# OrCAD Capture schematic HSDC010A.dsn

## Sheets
1 DATA: size B; title: TFP401EVM HSDC010; rev: A
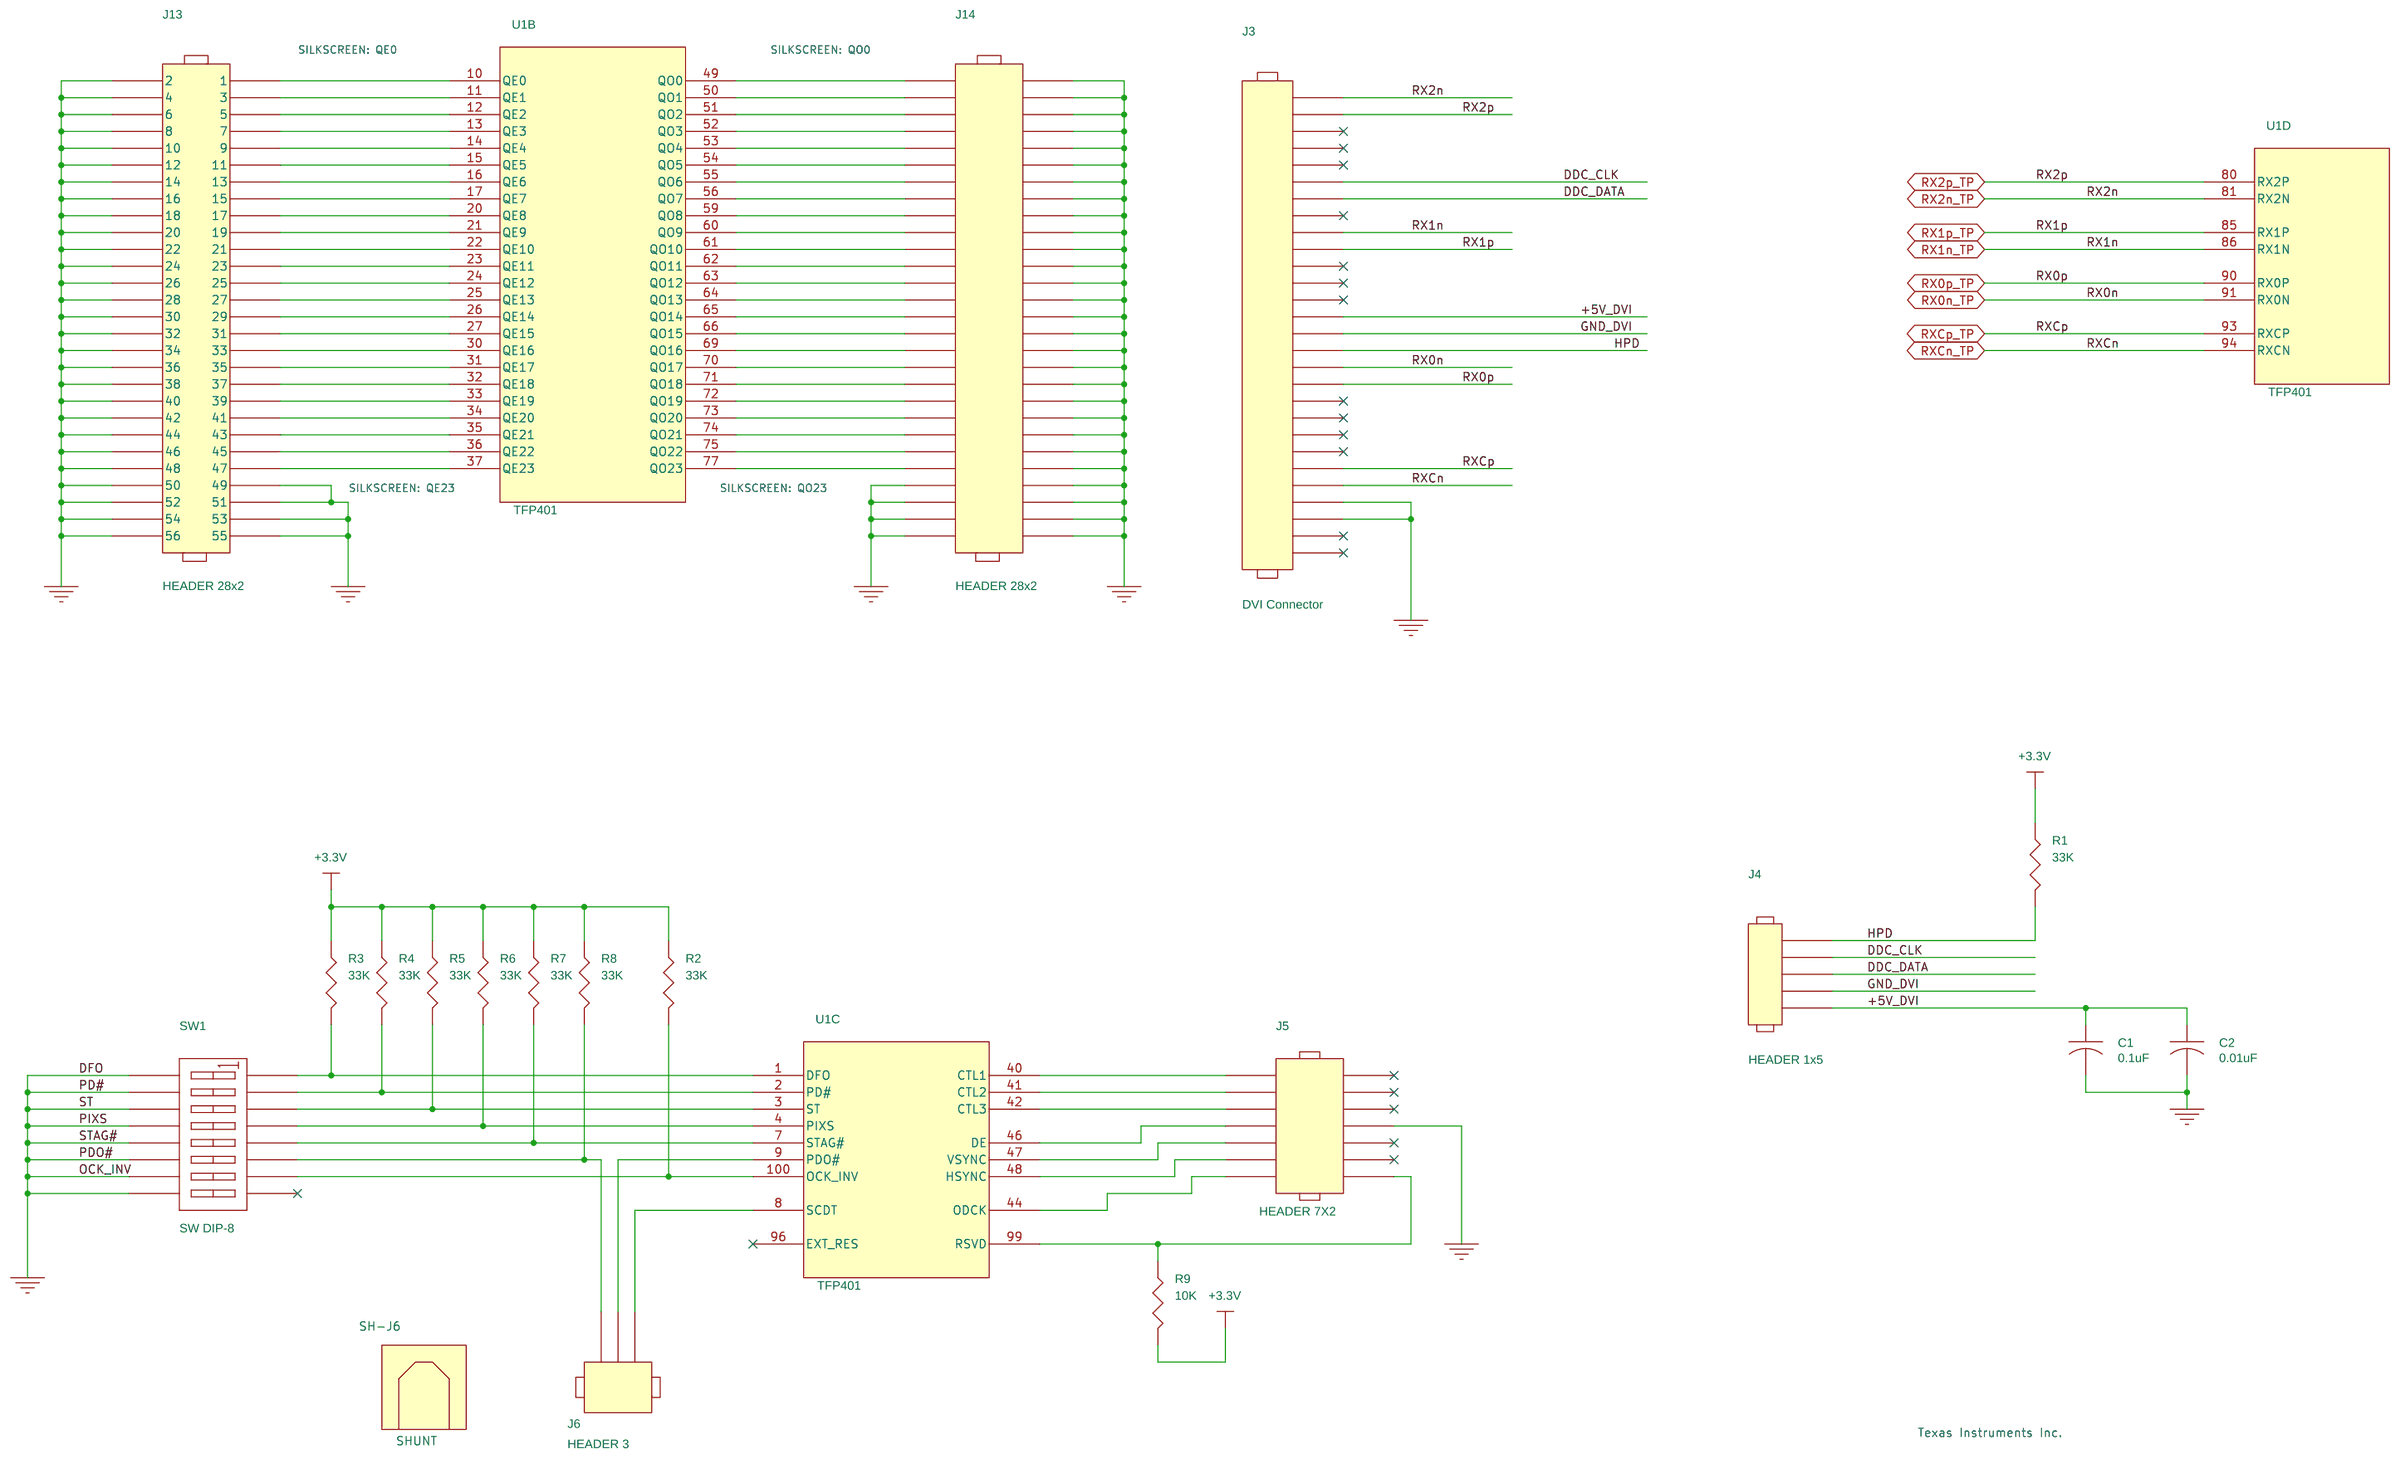
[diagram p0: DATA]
2 MISC: size B
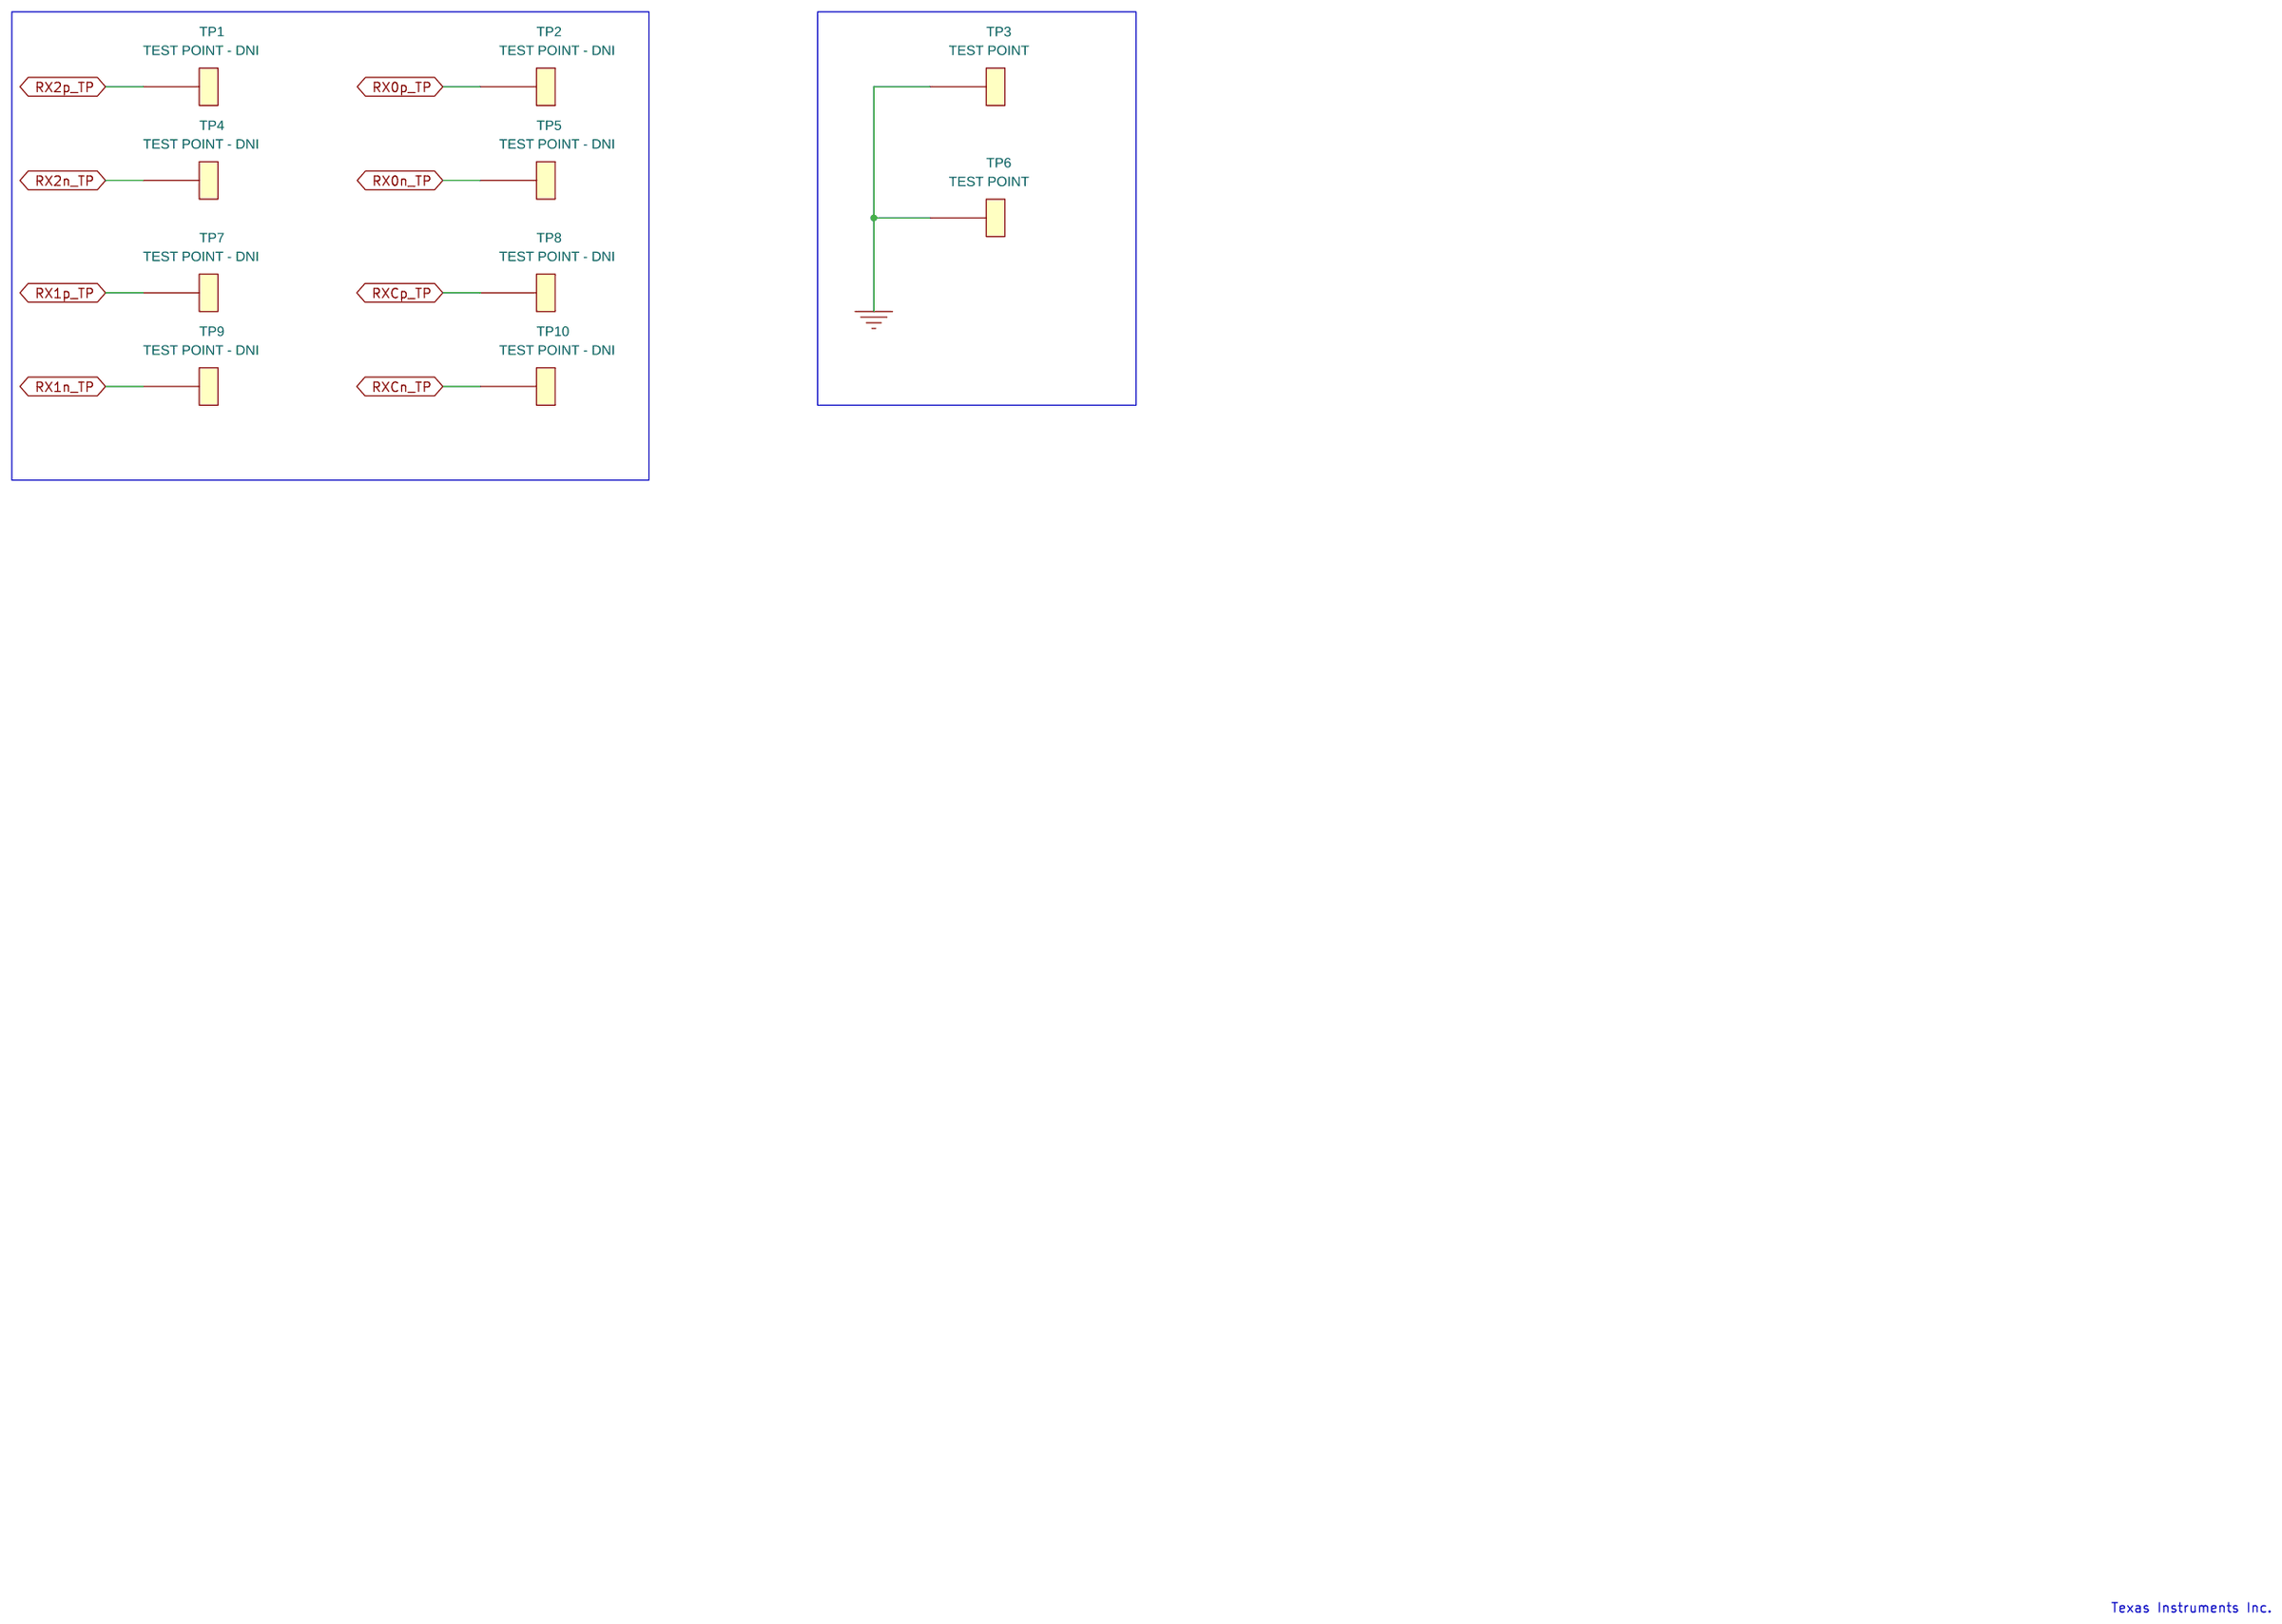
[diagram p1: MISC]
3 Power: size B
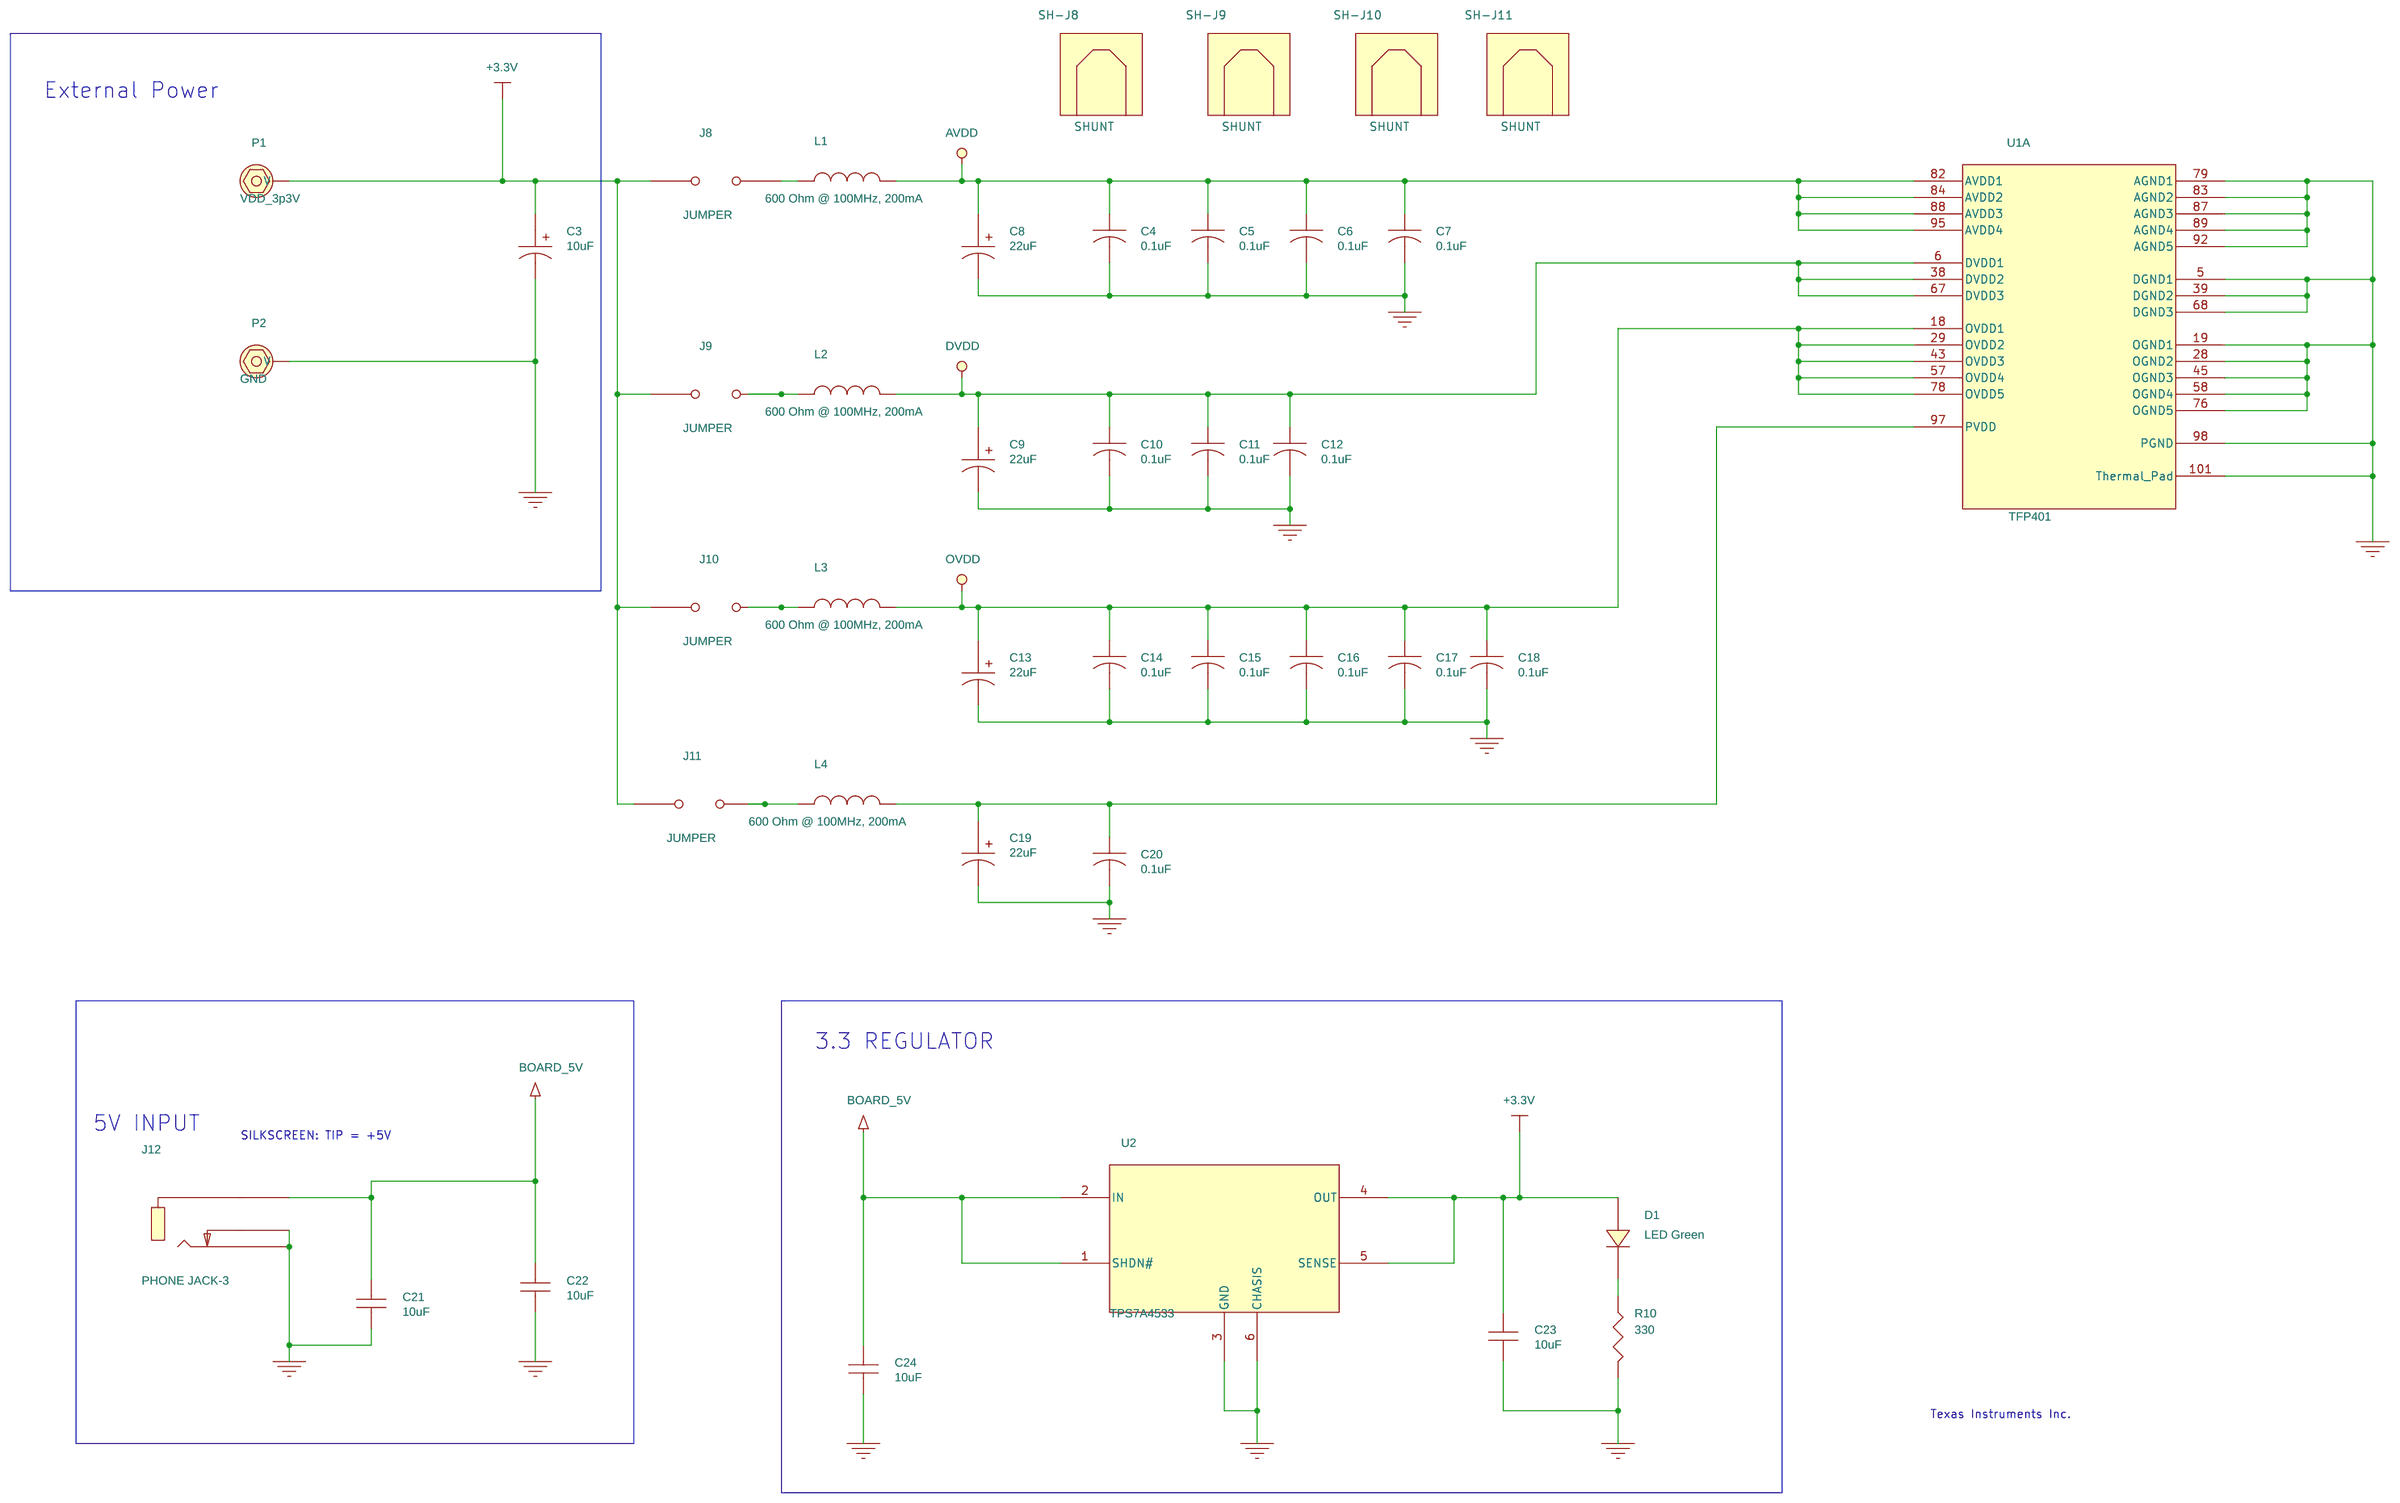
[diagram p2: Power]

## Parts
sheet DATA
C1  0.1uF  [cc0603]
C2  0.01uF  [cc0603]
J3  DVI Connector  [DVI_conn_01]
J4  HEADER 1x5  [berg1x5]
J5  HEADER 7X2  [berg2x7]
J6  HEADER 3  [hdr_thvt_1x3_100]
J13  HEADER 28x2  [header2x28]
J14  HEADER 28x2  [header2x28]
R1  33K  [r0402]
R2  33K  [r0402]
R3  33K  [r0402]
R4  33K  [r0402]
R5  33K  [r0402]
R6  33K  [r0402]
R7  33K  [r0402]
R8  33K  [r0402]
R9  10K  [r0402]
SH-J6  SHUNT
SW1  SW DIP-8  [TDA08H0SK1]
sheet MISC
TP1  TEST POINT - DNI  [TestPointSMT_1]
TP2  TEST POINT - DNI  [TestPointSMT_1]
TP3  TEST POINT  [berg1x1]
TP4  TEST POINT - DNI  [TestPointSMT_1]
TP5  TEST POINT - DNI  [TestPointSMT_1]
TP6  TEST POINT  [berg1x1]
TP7  TEST POINT - DNI  [TestPointSMT_1]
TP8  TEST POINT - DNI  [TestPointSMT_1]
TP9  TEST POINT - DNI  [TestPointSMT_1]
TP10  TEST POINT - DNI  [TestPointSMT_1]
sheet Power
C3  10uF  [cc0805]
C4  0.1uF  [cc0603]
C5  0.1uF  [cc0603]
C6  0.1uF  [cc0603]
C7  0.1uF  [cc0603]
C8  22uF  [cc0805]
C9  22uF  [cc0805]
C10  0.1uF  [cc0603]
C11  0.1uF  [cc0603]
C12  0.1uF  [cc0603]
C13  22uF  [cc0805]
C14  0.1uF  [cc0603]
C15  0.1uF  [cc0603]
C16  0.1uF  [cc0603]
C17  0.1uF  [cc0603]
C18  0.1uF  [cc0603]
C19  22uF  [cc0805]
C20  0.1uF  [cc0603]
C21  10uF  [cc0805]
C22  10uF  [cc0805]
C23  10uF  [cc0805]
C24  10uF  [cc0805]
D1  LED Green  [r0805]
J8  JUMPER  [berg1x2]
J9  JUMPER  [berg1x2]
J10  JUMPER  [berg1x2]
J11  JUMPER  [berg1x2]
J12  PHONE JACK-3  [PJ-202AH]
L1  600 Ohm @ 100MHz, 200mA  [CAP0603]
L2  600 Ohm @ 100MHz, 200mA  [CAP0603]
L3  600 Ohm @ 100MHz, 200mA  [CAP0603]
L4  600 Ohm @ 100MHz, 200mA  [CAP0603]
P1  Banana-Jack  [Banana_Jack_250mil]
P2  Banana-Jack  [Banana_Jack_250mil]
R10  330  [r0402]
SH-J8  SHUNT
SH-J9  SHUNT
SH-J10  SHUNT
SH-J11  SHUNT
U1  TFP401  [pzp-s-pqfp-g100]  (sections A,B,C,D)
U2  TPS7A4533  [dcq_r-pdso-g6]

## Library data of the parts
C1 C2 C4-C7 C10-C12 C14-C18 C20 = CAP
J3 = HEADER_28
J4 = HEADER_5
J5 = HEADER_7X2
J6 = HEADER_3
J13 = HEADER_28x2_0
J14 = HEADER_28x2
R1-R10 = R
SH-J6 SH-J8-SH-J11 = SHUNT
SW1 = SW_DIP-8
TP1 = TEST_POINT_0: Open pads
TP2 TP4 TP5 TP7-TP10 = TEST_POINT_0: OPEN PADS
TP3 TP6 = TEST_POINT_0: EST POINT PC MULTI PURPOSE BLK
C3 C8 C9 C13 C19 = CAP_POL
C21-C24 = CAP_NP
D1 = DIODE
J8-J11 = JUMPER
J12 = PHONE_JACK-3_0
L1-L4 = INDUCTOR
P1 = Banana-Jack: SILKTEXT1: VDD_3p3V; SILKTEXT2: VDD_3p3V
P2 = Banana-Jack: SILKTEXT1: GND; SILKTEXT2: GND
U1 = TFP401
U2 = TPS7A4533

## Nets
+3.3V: C3.1 C23.1 D1.2(A) J8.1 J9.1 J10.1 J11.1 P1.1(V) R1.1 R2.1 R3.1 R4.1 R5.1 R6.1 R7.1 R8.1 R9.2 U2.4(OUT) U2.5(SENSE)
+5V_DVI: C1.1 C2.1 J3.14 J4.5
AVDD: C4.1 C5.1 C6.1 C7.1 C8.1 L1.2 U1.82(AVDD1) U1.84(AVDD2) U1.88(AVDD3) U1.95(AVDD4)
DVDD: C9.1 C10.1 C11.1 C12.1 L2.2 U1.6(DVDD1) U1.38(DVDD2) U1.67(DVDD3)
GND_DVI: J3.15 J4.4
GND_POWER: C1.2 C2.2 C3.2 C4.2 C5.2 C6.2 C7.2 C8.2 C9.2 C10.2 C11.2 C12.2 C13.2 C14.2 C15.2 C16.2 C17.2 C18.2 C19.2 C20.2 C21.2 C22.2 C23.2 C24.2 J3.25 J3.26 J5.7 J12.2 J12.3 J13.1(55) J13.2(56) J13.3(53) J13.4(54) J13.5(51) J13.6(52) J13.7(49) J13.8(50) J13.10(48) J13.12(46) J13.14(44) J13.16(42) J13.18(40) J13.20(38) J13.22(36) J13.24(34) J13.26(32) J13.28(30) J13.30(28) J13.32(26) J13.34(24) J13.36(22) J13.38(20) J13.40(18) J13.42(16) J13.44(14) J13.46(12) J13.48(10) J13.50(8) J13.52(6) J13.54(4) J13.56(2) J14.1 J14.3 J14.5 J14.7 J14.9 J14.11 J14.13 J14.15 J14.17 J14.19 J14.21 J14.23 J14.25 J14.27 J14.29 J14.31 J14.33 J14.35 J14.37 J14.39 J14.41 J14.43 J14.45 J14.47 J14.49 J14.50 J14.51 J14.52 J14.53 J14.54 J14.55 J14.56 P2.1(V) R10.2 SW1.1(A1) SW1.2(A2) SW1.3(A3) SW1.4(A4) SW1.5(A5) SW1.6(A6) SW1.7(A7) SW1.8(A8) TP3.1 TP6.1 U1.5(DGND1) U1.19(OGND1) U1.28(OGND2) U1.39(DGND2) U1.45(OGND3) U1.58(OGND4) U1.68(DGND3) U1.76(OGND5) U1.79(AGND1) U1.83(AGND2) U1.87(AGND3) U1.89(AGND4) U1.92(AGND5) U1.98(PGND) U1.101(Thermal_Pad) U2.3(GND) U2.6(CHASIS)
BOARD_5V: C21.1 C22.1 C24.1 J12.1 U2.1(SHDN#) U2.2(IN)
DDC_CLK: J3.6 J4.2
DDC_DATA: J3.7 J4.3
HPD: J3.16 J4.1 R1.2
OVDD: C13.1 C14.1 C15.1 C16.1 C17.1 C18.1 L3.2 U1.18(OVDD1) U1.29(OVDD2) U1.43(OVDD3) U1.57(OVDD4) U1.78(OVDD5)
RX0n_TP: J3.17 TP5.1 U1.91(RX0N)
RX0p_TP: J3.18 TP2.1 U1.90(RX0P)
RX1n_TP: J3.9 TP9.1 U1.86(RX1N)
RX1p_TP: J3.10 TP7.1 U1.85(RX1P)
RX2n_TP: J3.1 TP4.1 U1.81(RX2N)
RX2p_TP: J3.2 TP1.1 U1.80(RX2P)
RXCn_TP: J3.24 TP10.1 U1.94(RXCN)
RXCp_TP: J3.23 TP8.1 U1.93(RXCP)
N03879: C19.1 C20.1 L4.2 U1.97(PVDD)
N04328: J9.2 L2.1
N04342: J10.2 L3.1
N04358: J11.2 L4.1
N05960: J13.55(1) U1.10(QE0)
N05964: J13.53(3) U1.11(QE1)
N05968: J13.51(5) U1.12(QE2)
N05972: J13.49(7) U1.13(QE3)
N05976: J13.47(9) U1.14(QE4)
N05980: J13.45(11) U1.15(QE5)
N05984: J13.43(13) U1.16(QE6)
N05988: J13.41(15) U1.17(QE7)
N05992: J13.39(17) U1.20(QE8)
N05996: J13.37(19) U1.21(QE9)
N06000: J13.35(21) U1.22(QE10)
N06004: J13.33(23) U1.23(QE11)
N06008: J13.31(25) U1.24(QE12)
N06012: J13.29(27) U1.25(QE13)
N06016: J13.27(29) U1.26(QE14)
N06020: J13.25(31) U1.27(QE15)
N06024: J13.23(33) U1.30(QE16)
N06028: J13.21(35) U1.31(QE17)
N06032: J13.19(37) U1.32(QE18)
N06036: J13.17(39) U1.33(QE19)
N06040: J13.15(41) U1.34(QE20)
N06044: J13.13(43) U1.35(QE21)
N06048: J13.11(45) U1.36(QE22)
N06052: J13.9(47) U1.37(QE23)
N06056: J14.48 U1.77(QO23)
N06060: J14.46 U1.75(QO22)
N06064: J14.44 U1.74(QO21)
N06068: J14.42 U1.73(QO20)
N06072: J14.40 U1.72(QO19)
N06076: J14.38 U1.71(QO18)
N06080: J14.36 U1.70(QO17)
N06084: J14.34 U1.69(QO16)
N06088: J14.32 U1.66(QO15)
N06092: J14.30 U1.65(QO14)
N06096: J14.28 U1.64(QO13)
N06100: J14.26 U1.63(QO12)
N06104: J14.24 U1.62(QO11)
N06108: J14.22 U1.61(QO10)
N06112: J14.20 U1.60(QO9)
N06116: J14.18 U1.59(QO8)
N06120: J14.16 U1.56(QO7)
N06124: J14.14 U1.55(QO6)
N06128: J14.12 U1.54(QO5)
N06132: J14.10 U1.53(QO4)
N06136: J14.8 U1.52(QO3)
N06140: J14.6 U1.51(QO2)
N06144: J14.4 U1.50(QO1)
N06148: J14.2 U1.49(QO0)
N13798: R3.2 SW1.16(B1) U1.1(DFO)
N13802: R4.2 SW1.15(B2) U1.2(PD#)
N13806: R5.2 SW1.14(B3) U1.3(ST)
N13810: R6.2 SW1.13(B4) U1.4(PIXS)
N13814: R7.2 SW1.12(B5) U1.7(STAG#)
N13818: J6.1 R8.2 SW1.11(B6)
N13822: R2.2 SW1.10(B7) U1.100(OCK_INV)
N14714: J6.2 U1.9(PDO#)
N14769: J6.3 U1.8(SCDT)
N17734: J5.14 U1.44(ODCK)
N17746: J5.12 U1.48(HSYNC)
N17750: J5.10 U1.47(VSYNC)
N17754: J5.8 U1.46(DE)
N17758: J5.6 U1.42(CTL3)
N17762: J5.4 U1.41(CTL2)
N17766: J5.2 U1.40(CTL1)
N17770: J5.13 R9.1 U1.99(RSVD)
N35472: D1.1(K) R10.1
N40612: J8.2 L1.1

Not connected (* = marked no-connect by the designer): J3 3* 4* 5* 8* 11* 12* 13* 19* 20* 21* 22* 27* 28*; J5 1* 3* 5* 9* 11*; SW1 9(B8)*; U1 96(EXT_RES)*

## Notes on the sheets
sheet 1
- SILKSCREEN: QE0
- SILKSCREEN: QO0
- SILKSCREEN: QE23
- SILKSCREEN: QO23
- Texas Instruments Inc.
sheet 2
- Texas Instruments Inc.
sheet 3
- External Power
- 3.3 REGULATOR
- 5V INPUT
- SILKSCREEN: TIP = +5V
- Texas Instruments Inc.
